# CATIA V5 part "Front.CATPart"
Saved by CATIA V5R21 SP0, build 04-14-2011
Part number: Front
Bounding box of the stored display mesh (mm): x 0 to 2.8, y -92.8 to 92.8, z -5 to 60
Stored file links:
  C:\Users\Pouria\Desktop\Box\Assembled\Front.CATPart
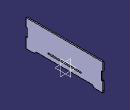
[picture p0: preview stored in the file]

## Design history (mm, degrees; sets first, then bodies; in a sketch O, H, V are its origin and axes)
Body1 (main body)
  Sketch1 on yz-plane, origin (0, 0, 0), H (0, 1, 0), V (0, 0, 1)
    point P1 (-92.8, 0)
    line L1 (-67.8, 0) -> (67.8, 0)
    line L2 (92.8, 0) -> (92.8, 20)
    line L3 (92.8, 60) -> (-92.8, 60)
    line L4 (-92.8, 60) -> (-92.8, 40)
    point P2 (92.8, 0)
    point P3 (92.8, 60)
    point P5 (92.8, 40)
    line L5 (92.8, 40) -> (90, 40)
    line L6 (90, 40) -> (90, 20)
    line L7 (90, 20) -> (92.8, 20)
    line L8 (-92.8, 40) -> (-90, 40)
    line L9 (-90, 40) -> (-90, 20)
    line L10 (-90, 20) -> (-92.8, 20)
    point P12 (-92.8, 20)
    line L11 (67.8, 0) -> (72.8, -5)
    line L12 (72.8, -5) -> (92.8, -5)
    point P15 (92.8, -5)
    line L13 (92.8, -5) -> (92.8, 0)
    line L14 (-92.8, 0) -> (-92.8, -5)
    line L15 (-92.8, -5) -> (-72.8, -5)
    line L16 (-72.8, -5) -> (-67.8, 0)
    line L17 (92.8, 40) -> (92.8, 60)
    line L18 (-92.8, 20) -> (-92.8, 0)
    point P19 (0, 11.4)
    line L19 (40, 12.8) -> (40, 10)
    line L20 (40, 10) -> (-40, 10)
    line L21 (-40, 10) -> (-40, 12.8)
    line L22 (-40, 12.8) -> (40, 12.8)
    length L3 = 185.6
    length L6 = 20
    length L9 = 20
    length L5 = 2.8
    length L8 = 2.8
    distance L7 L1 = 20
    distance L10 L1 = 20
    length L12 = 20
    length L13 = 5
    length L15 = 20
    length L14 = 5
    angle L11 L1 = 45
    angle L16 L1 = 45
    distance P2 P3 = 60
    distance L20 L1 = 10
    length L19 = 2.8
    length L22 = 80
    coincidence: P1 H, P5 L2, P12 L4, P15 L2, L1 H, P2 H, L2 L17, L4 L18, P19 V
    horizontal: L1 H, L3 H, L5 H, L7 H, L8 H, L10 H, L12 H, L15 H, L20 H, L22 H
    vertical: L2 V, L4 V, L6 V, L9 V, L13 V, L14 V, L17 V, L18 V, L19 V, L21 V
    symmetry: L2 L4 V
    equidistance: L19 L21 P19, L20 L22 P19
  Pad1: profile Sketch1, direction (1, 0, 0), length 2.8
